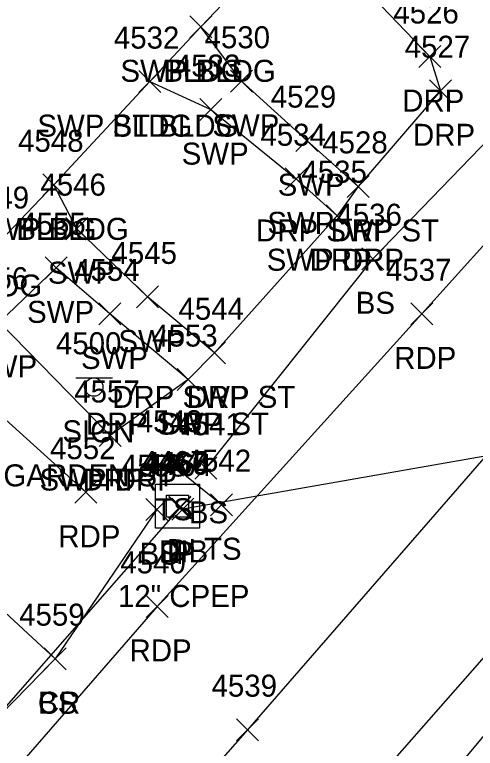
# Model space of a CAD drawing. Extents: x 1653135 to 1655489, y 602711 to 605684.
# Drawn here: x 1653195.4 to 1653237.3, y 604853.4 to 604920.1 of the extents above; entities that cross this region are included whole.
import ezdxf

# ---------------------------------------------------------------- set-up
doc = ezdxf.new("R2010")
doc.units = 0
for name, color, linetype in [('D_A', 7, 'Continuous'), ('D_C', 7, 'Continuous'), ('D_I', 7, 'Continuous'), ('D_TIC', 7, 'Continuous'), ('DCP', 7, 'Continuous'), ('DS', 7, 'Continuous'), ('L_A', 7, 'Continuous'), ('L_I', 7, 'Continuous'), ('L_TIC', 7, 'Continuous'), ('LBC', 7, 'Continuous'), ('LELB', 7, 'Continuous'), ('P_A', 7, 'Continuous'), ('P_I', 7, 'Continuous'), ('P_TIC', 7, 'Continuous'), ('PET', 7, 'Continuous'), ('PRC', 7, 'Continuous'), ('PSP', 7, 'Continuous'), ('R_A', 7, 'Continuous'), ('R_I', 7, 'Continuous'), ('R_TIC', 7, 'Continuous'), ('RDP', 7, 'Continuous'), ('RSW', 7, 'Continuous'), ('S_A', 7, 'Continuous'), ('S_C', 7, 'Continuous'), ('S_I', 7, 'Continuous'), ('SSGN', 7, 'Continuous')]:
    doc.layers.add(name, color=color, linetype=linetype)

msp = doc.modelspace()

# ---------------------------------------------------------------- linework, layer by layer
at = {"layer": 'D_TIC'}
for points in [[(1653209.407, 604874.267), (1653211.407, 604876.267)], [(1653211.407, 604874.267), (1653209.407, 604876.267)], [(1653209.407, 604874.267), (1653211.407, 604876.267)], [(1653211.407, 604874.267), (1653209.407, 604876.267)], [(1653209.428, 604874.33), (1653211.428, 604876.33)], [(1653211.428, 604874.33), (1653209.428, 604876.33)], [(1653209.428, 604874.33), (1653211.428, 604876.33)], [(1653211.428, 604874.33), (1653209.428, 604876.33)], [(1653209.682, 604874.162), (1653211.682, 604876.162)], [(1653211.682, 604874.162), (1653209.682, 604876.162)], [(1653209.682, 604874.162), (1653211.682, 604876.162)], [(1653211.682, 604874.162), (1653209.682, 604876.162)]]:
    msp.add_lwpolyline(points, dxfattribs=at)
at = {"layer": 'DCP'}
for points in [[(1653256.839, 604883.252), (1653210.682, 604875.162)], [(1653210.407, 604875.267), (1653189.689, 604851.651)]]:
    msp.add_lwpolyline(points, dxfattribs=at)
at = {"layer": 'DS'}
for p, q in [((1653208.191, 604877.425), (1653212.191, 604877.425)), ((1653208.191, 604873.425), (1653208.191, 604877.425)), ((1653212.191, 604877.425), (1653212.191, 604873.425)), ((1653209.191, 604874.425), (1653209.191, 604876.425)), ((1653209.191, 604876.425), (1653211.191, 604876.425)), ((1653211.191, 604876.425), (1653211.191, 604874.425)), ((1653210.196, 604875.426), (1653210.196, 604875.426)), ((1653210.196, 604875.426), (1653210.196, 604875.426)), ((1653211.191, 604874.425), (1653209.191, 604874.425)), ((1653212.191, 604873.425), (1653208.191, 604873.425))]:
    msp.add_line(p, q, dxfattribs=at)
at = {"layer": 'L_TIC'}
for points in [[(1653211.334, 604917.975), (1653213.334, 604919.975)], [(1653213.334, 604917.975), (1653211.334, 604919.975)], [(1653211.334, 604917.975), (1653213.334, 604919.975)], [(1653213.334, 604917.975), (1653211.334, 604919.975)], [(1653206.681, 604912.994), (1653208.681, 604914.994)], [(1653208.681, 604912.994), (1653206.681, 604914.994)], [(1653206.681, 604912.994), (1653208.681, 604914.994)], [(1653208.681, 604912.994), (1653206.681, 604914.994)], [(1653197.974, 604903.617), (1653199.974, 604905.617)], [(1653199.974, 604903.617), (1653197.974, 604905.617)], [(1653197.974, 604903.617), (1653199.974, 604905.617)], [(1653199.974, 604903.617), (1653197.974, 604905.617)], [(1653226.961, 604896.9), (1653228.961, 604898.9)], [(1653228.961, 604896.9), (1653226.961, 604898.9)], [(1653226.961, 604896.9), (1653228.961, 604898.9)], [(1653228.961, 604896.9), (1653226.961, 604898.9)], [(1653208.757, 604878.141), (1653210.757, 604880.141)], [(1653210.757, 604878.141), (1653208.757, 604880.141)], [(1653208.757, 604878.141), (1653210.757, 604880.141)], [(1653210.757, 604878.141), (1653208.757, 604880.141)], [(1653211.791, 604877.867), (1653213.791, 604879.867)], [(1653213.791, 604877.867), (1653211.791, 604879.867)], [(1653211.791, 604877.867), (1653213.791, 604879.867)], [(1653213.791, 604877.867), (1653211.791, 604879.867)], [(1653207.322, 604874.113), (1653209.322, 604876.113)], [(1653209.322, 604874.113), (1653207.322, 604876.113)], [(1653207.322, 604874.113), (1653209.322, 604876.113)], [(1653209.322, 604874.113), (1653207.322, 604876.113)], [(1653213.202, 604874.555), (1653215.202, 604876.555)], [(1653215.202, 604874.555), (1653213.202, 604876.555)], [(1653213.202, 604874.555), (1653215.202, 604876.555)], [(1653215.202, 604874.555), (1653213.202, 604876.555)], [(1653198.083, 604860.566), (1653200.083, 604862.566)], [(1653200.083, 604860.566), (1653198.083, 604862.566)], [(1653198.083, 604860.566), (1653200.083, 604862.566)], [(1653200.083, 604860.566), (1653198.083, 604862.566)]]:
    msp.add_lwpolyline(points, dxfattribs=at)
at = {"layer": 'LBC'}
msp.add_lwpolyline([(1653219.995, 604933.479), (1653223.222, 604930.634), (1653221.419, 604928.498), (1653212.334, 604918.975), (1653207.681, 604913.994), (1653198.974, 604904.617), (1653194.036, 604899.465), (1653189.6, 604903.61)], dxfattribs=at)
at = {"layer": 'LELB'}
for points in [[(1653332.421, 605013.129), (1653331.89, 605009.978), (1653320.371, 604996.763), (1653305.472, 604980.516), (1653289.085, 604960.14), (1653269.848, 604940.864), (1653246.658, 604917.207), (1653227.961, 604897.9), (1653212.791, 604878.867)], [(1653214.202, 604875.555), (1653209.757, 604879.141)], [(1653208.322, 604875.113), (1653199.083, 604861.566), (1653190.334, 604852.619), (1653187.506, 604849.984), (1653174.107, 604834.568), (1653155.579, 604815.865)]]:
    msp.add_lwpolyline(points, dxfattribs=at)
at = {"layer": 'P_TIC'}
for points in [[(1653231.406, 604891.896), (1653233.406, 604893.896)], [(1653233.406, 604891.896), (1653231.406, 604893.896)], [(1653231.406, 604891.896), (1653233.406, 604893.896)], [(1653233.406, 604891.896), (1653231.406, 604893.896)], [(1653200.882, 604875.692), (1653202.882, 604877.692)], [(1653202.882, 604875.692), (1653200.882, 604877.692)], [(1653200.882, 604875.692), (1653202.882, 604877.692)], [(1653202.882, 604875.692), (1653200.882, 604877.692)], [(1653207.357, 604865.317), (1653209.357, 604867.317)], [(1653209.357, 604865.317), (1653207.357, 604867.317)], [(1653207.357, 604865.317), (1653209.357, 604867.317)], [(1653209.357, 604865.317), (1653207.357, 604867.317)], [(1653198.083, 604860.566), (1653200.083, 604862.566)], [(1653200.083, 604860.566), (1653198.083, 604862.566)], [(1653198.083, 604860.566), (1653200.083, 604862.566)], [(1653200.083, 604860.566), (1653198.083, 604862.566)], [(1653215.566, 604854.116), (1653217.566, 604856.116)], [(1653217.566, 604854.116), (1653215.566, 604856.116)], [(1653215.566, 604854.116), (1653217.566, 604856.116)], [(1653217.566, 604854.116), (1653215.566, 604856.116)]]:
    msp.add_lwpolyline(points, dxfattribs=at)
at = {"layer": 'PET'}
for points in [[(1653570.485, 605162.786), (1653545.403, 605152.188), (1653524.597, 605144.335), (1653501.66, 605134.239), (1653492.53, 605129.6), (1653483.217, 605126.16), (1653461.507, 605114.196), (1653431.751, 605097.051), (1653402.439, 605074.196), (1653383.496, 605058.488), (1653369.863, 605045.734), (1653350.113, 605021.59), (1653336.009, 605007.549), (1653322.852, 604993.824), (1653302.166, 604970.774), (1653290.93, 604958.375), (1653272.167, 604938.098), (1653250.651, 604913.142), (1653232.406, 604892.896), (1653208.357, 604866.317), (1653177.81, 604831.245), (1653160.535, 604811.983)], [(1653576.316, 605135.262), (1653553.767, 605126.837), (1653519.051, 605112.425), (1653493.535, 605100.339), (1653468.833, 605088.005), (1653447.853, 605075.02), (1653427.596, 605061.865), (1653406.781, 605044.605), (1653388.905, 605027.698), (1653366.499, 605004.888), (1653354.584, 604992.023), (1653334.896, 604970.66), (1653318.046, 604952.193), (1653296.488, 604928.187), (1653274.624, 604903.556), (1653244.239, 604868.756), (1653225.75, 604847.701), (1653206.334, 604825.65), (1653179.645, 604794.747)], [(1653179.967, 604896.477), (1653201.882, 604876.692)]]:
    msp.add_lwpolyline(points, dxfattribs=at)
at = {"layer": 'PRC'}
for points in [[(1653576.361, 605149.524), (1653550.317, 605139.021), (1653518.724, 605125.668), (1653498.017, 605116.666), (1653468.035, 605101.489), (1653440.124, 605084.852), (1653411.973, 605063.454), (1653392.179, 605045.924), (1653380.925, 605035.31), (1653360.25, 605013.969), (1653332.49, 604984.793), (1653311.146, 604961.542), (1653300.12, 604949.228), (1653281.614, 604928.677), (1653260.957, 604905.277), (1653242.089, 604884.435), (1653216.566, 604855.116), (1653187.493, 604822.135), (1653170.081, 604802.31)], [(1653199.083, 604861.566), (1653169.543, 604888.888)]]:
    msp.add_lwpolyline(points, dxfattribs=at)
at = {"layer": 'PSP'}
msp.add_lwpolyline([(1653577.495, 605132.222), (1653555.735, 605120.61), (1653541.776, 605115.966), (1653532.613, 605114.781), (1653532.247, 605110.88), (1653522.733, 605106.898), (1653507.697, 605103.522), (1653493.111, 605096.605), (1653471.403, 605083.027), (1653450.958, 605070.25), (1653430.837, 605057.523), (1653410.321, 605040.006), (1653392.797, 605023.713), (1653372.132, 605001.835), (1653359.179, 604987.803), (1653339.003, 604967.206), (1653322.133, 604948.589), (1653300.744, 604925.192), (1653278.521, 604900.611), (1653247.528, 604865.908), (1653229.566, 604844.432), (1653209.3, 604822.581), (1653182.433, 604791.771)], dxfattribs=at)
at = {"layer": 'R_TIC'}
for points in [[(1653211.334, 604917.975), (1653213.334, 604919.975)], [(1653213.334, 604917.975), (1653211.334, 604919.975)], [(1653211.334, 604917.975), (1653213.334, 604919.975)], [(1653213.334, 604917.975), (1653211.334, 604919.975)], [(1653232.134, 604915.272), (1653234.134, 604917.272)], [(1653234.134, 604915.272), (1653232.134, 604917.272)], [(1653232.134, 604915.272), (1653234.134, 604917.272)], [(1653234.134, 604915.272), (1653232.134, 604917.272)], [(1653206.681, 604912.994), (1653208.681, 604914.994)], [(1653208.681, 604912.994), (1653206.681, 604914.994)], [(1653206.681, 604912.994), (1653208.681, 604914.994)], [(1653208.681, 604912.994), (1653206.681, 604914.994)], [(1653215.009, 604913.024), (1653217.009, 604915.024)], [(1653217.009, 604913.024), (1653215.009, 604915.024)], [(1653215.009, 604913.024), (1653217.009, 604915.024)], [(1653217.009, 604913.024), (1653215.009, 604915.024)], [(1653233.115, 604912.162), (1653235.115, 604914.162)], [(1653235.115, 604912.162), (1653233.115, 604914.162)], [(1653233.115, 604912.162), (1653235.115, 604914.162)], [(1653235.115, 604912.162), (1653233.115, 604914.162)], [(1653212.222, 604910.455), (1653214.222, 604912.455)], [(1653214.222, 604910.455), (1653212.222, 604912.455)], [(1653212.222, 604910.455), (1653214.222, 604912.455)], [(1653214.222, 604910.455), (1653212.222, 604912.455)], [(1653220.944, 604907.632), (1653222.944, 604909.632)], [(1653222.944, 604907.632), (1653220.944, 604909.632)], [(1653220.944, 604907.632), (1653222.944, 604909.632)], [(1653222.944, 604907.632), (1653220.944, 604909.632)], [(1653220.002, 604904.164), (1653222.002, 604906.164)], [(1653222.002, 604904.164), (1653220.002, 604906.164)], [(1653220.002, 604904.164), (1653222.002, 604906.164)], [(1653222.002, 604904.164), (1653220.002, 604906.164)], [(1653197.974, 604903.617), (1653199.974, 604905.617)], [(1653199.974, 604903.617), (1653197.974, 604905.617)], [(1653197.974, 604903.617), (1653199.974, 604905.617)], [(1653199.974, 604903.617), (1653197.974, 604905.617)], [(1653225.618, 604903.474), (1653227.618, 604905.474)], [(1653227.618, 604903.474), (1653225.618, 604905.474)], [(1653225.618, 604903.474), (1653227.618, 604905.474)], [(1653227.618, 604903.474), (1653225.618, 604905.474)], [(1653225.618, 604903.474), (1653227.618, 604905.474)], [(1653227.618, 604903.474), (1653225.618, 604905.474)], [(1653225.618, 604903.474), (1653227.618, 604905.474)], [(1653227.618, 604903.474), (1653225.618, 604905.474)], [(1653223.727, 604900.812), (1653225.727, 604902.812)], [(1653225.727, 604900.812), (1653223.727, 604902.812)], [(1653223.727, 604900.812), (1653225.727, 604902.812)], [(1653225.727, 604900.812), (1653223.727, 604902.812)], [(1653223.727, 604900.812), (1653225.727, 604902.812)], [(1653225.727, 604900.812), (1653223.727, 604902.812)], [(1653223.727, 604900.812), (1653225.727, 604902.812)], [(1653225.727, 604900.812), (1653223.727, 604902.812)], [(1653200.061, 604899.635), (1653202.061, 604901.635)], [(1653202.061, 604899.635), (1653200.061, 604901.635)], [(1653200.061, 604899.635), (1653202.061, 604901.635)], [(1653202.061, 604899.635), (1653200.061, 604901.635)], [(1653198.171, 604896.077), (1653200.171, 604898.077)], [(1653200.171, 604896.077), (1653198.171, 604898.077)], [(1653198.171, 604896.077), (1653200.171, 604898.077)], [(1653200.171, 604896.077), (1653198.171, 604898.077)], [(1653206.465, 604893.435), (1653208.465, 604895.435)], [(1653208.465, 604893.435), (1653206.465, 604895.435)], [(1653206.465, 604893.435), (1653208.465, 604895.435)], [(1653208.465, 604893.435), (1653206.465, 604895.435)], [(1653203.069, 604891.891), (1653205.069, 604893.891)], [(1653205.069, 604891.891), (1653203.069, 604893.891)], [(1653203.069, 604891.891), (1653205.069, 604893.891)], [(1653205.069, 604891.891), (1653203.069, 604893.891)], [(1653212.552, 604888.356), (1653214.552, 604890.356)], [(1653214.552, 604888.356), (1653212.552, 604890.356)], [(1653212.552, 604888.356), (1653214.552, 604890.356)], [(1653214.552, 604888.356), (1653212.552, 604890.356)], [(1653212.552, 604888.356), (1653214.552, 604890.356)], [(1653214.552, 604888.356), (1653212.552, 604890.356)], [(1653212.552, 604888.356), (1653214.552, 604890.356)], [(1653214.552, 604888.356), (1653212.552, 604890.356)], [(1653210.159, 604885.923), (1653212.159, 604887.923)], [(1653212.159, 604885.923), (1653210.159, 604887.923)], [(1653210.159, 604885.923), (1653212.159, 604887.923)], [(1653212.159, 604885.923), (1653210.159, 604887.923)], [(1653210.159, 604885.923), (1653212.159, 604887.923)], [(1653212.159, 604885.923), (1653210.159, 604887.923)], [(1653210.159, 604885.923), (1653212.159, 604887.923)], [(1653212.159, 604885.923), (1653210.159, 604887.923)], [(1653203.08, 604880.842), (1653205.08, 604882.842)], [(1653205.08, 604880.842), (1653203.08, 604882.842)], [(1653203.08, 604880.842), (1653205.08, 604882.842)], [(1653205.08, 604880.842), (1653203.08, 604882.842)], [(1653203.08, 604880.842), (1653205.08, 604882.842)], [(1653205.08, 604880.842), (1653203.08, 604882.842)], [(1653203.08, 604880.842), (1653205.08, 604882.842)], [(1653205.08, 604880.842), (1653203.08, 604882.842)]]:
    msp.add_lwpolyline(points, dxfattribs=at)
at = {"layer": 'RDP'}
msp.add_lwpolyline([(1653221.419, 604928.498), (1653233.134, 604916.272), (1653234.115, 604913.162), (1653226.618, 604904.474), (1653224.727, 604901.812), (1653213.552, 604889.356), (1653211.159, 604886.923), (1653204.08, 604881.842)], dxfattribs=at)
at = {"layer": 'RSW'}
for points in [[(1653226.618, 604904.474), (1653221.944, 604908.632), (1653216.009, 604914.024), (1653212.334, 604918.975)], [(1653207.681, 604913.994), (1653213.222, 604911.455), (1653221.002, 604905.164), (1653224.727, 604901.812)], [(1653213.552, 604889.356), (1653207.465, 604894.435), (1653201.061, 604900.635), (1653198.974, 604904.617)], [(1653211.159, 604886.923), (1653204.069, 604892.891), (1653199.171, 604897.077), (1653193.995, 604892.133), (1653204.08, 604881.842)]]:
    msp.add_lwpolyline(points, dxfattribs=at)
at = {"layer": 'SSGN'}
for p, q in [((1653200.954, 604887.077), (1653204.287, 604887.077)), ((1653202.6, 604886.244), (1653202.6, 604886.244))]:
    msp.add_line(p, q, dxfattribs=at)
msp.add_circle((1653202.6, 604886.244), 0.833, dxfattribs=at)

# ---------------------------------------------------------------- texts
at = {"layer": 'D_A'}
for s, p in [('DIB', (1653208.53, 604870.33)), ('DIB', (1653208.53, 604870.33)), ('DI', (1653209.252, 604870.426)), ('P', (1653209.785, 604870.267)), ('P', (1653209.785, 604870.267)), ('P', (1653210.06, 604870.162)), ('P', (1653210.06, 604870.162))]:
    msp.add_text(s, height=2, dxfattribs=at).set_placement(p)
at = {"layer": 'D_C'}
msp.add_text('12" CPEP', height=2, dxfattribs=at).set_placement((1653204.793, 604866.267))
msp.add_text('12" CPEP', height=2, dxfattribs=at).set_placement((1653204.793, 604866.267))
at = {"layer": 'D_I'}
for s, p in [('4467', (1653206.889, 604878.426)), ('4466', (1653207.045, 604878.267)), ('4466', (1653207.045, 604878.267)), ('4465', (1653207.121, 604878.33)), ('4465', (1653207.121, 604878.33)), ('4464', (1653207.375, 604878.162)), ('4464', (1653207.375, 604878.162))]:
    msp.add_text(s, height=2, dxfattribs=at).set_placement(p)
at = {"layer": 'L_A'}
for s, p in [('BLDG', (1653208.924, 604913.975)), ('BLDG', (1653208.924, 604913.975)), ('BLDG', (1653204.271, 604908.994)), ('BLDG', (1653204.271, 604908.994)), ('BLDG', (1653195.565, 604899.617)), ('BLDG', (1653195.565, 604899.617)), ('BLDG', (1653190.627, 604894.465)), ('BLDG', (1653190.627, 604894.465)), ('BS', (1653226.402, 604892.9)), ('BS', (1653226.402, 604892.9)), ('TS', (1653208.167, 604874.141)), ('TS', (1653208.167, 604874.141)), ('BS', (1653211.232, 604873.867)), ('BS', (1653211.232, 604873.867)), ('TS', (1653212.612, 604870.555)), ('TS', (1653212.612, 604870.555)), ('BS', (1653206.763, 604870.113)), ('BS', (1653206.763, 604870.113)), ('BS', (1653197.524, 604856.566)), ('BS', (1653197.524, 604856.566))]:
    msp.add_text(s, height=2, dxfattribs=at).set_placement(p)
at = {"layer": 'L_I'}
for s, p in [('4532', (1653204.421, 604916.994)), ('4532', (1653204.421, 604916.994)), ('4548', (1653195.715, 604907.617)), ('4548', (1653195.715, 604907.617)), ('4549', (1653190.769, 604902.465)), ('4549', (1653190.769, 604902.465)), ('4536', (1653224.646, 604900.9)), ('4536', (1653224.646, 604900.9)), ('4543', (1653206.498, 604882.141)), ('4543', (1653206.498, 604882.141)), ('4541', (1653210.098, 604881.867)), ('4541', (1653210.098, 604881.867)), ('4542', (1653210.943, 604878.555)), ('4542', (1653210.943, 604878.555)), ('4558', (1653205.063, 604878.113)), ('4558', (1653205.063, 604878.113)), ('4559', (1653195.815, 604864.566)), ('4559', (1653195.815, 604864.566))]:
    msp.add_text(s, height=2, dxfattribs=at).set_placement(p)
at = {"layer": 'P_A'}
for s, p in [('RDP', (1653229.894, 604887.896)), ('RDP', (1653229.894, 604887.896)), ('RDP', (1653199.37, 604871.692)), ('RDP', (1653199.37, 604871.692)), ('RDP', (1653205.845, 604861.317)), ('RDP', (1653205.845, 604861.317)), ('CR', (1653197.516, 604856.566)), ('CR', (1653197.516, 604856.566))]:
    msp.add_text(s, height=2, dxfattribs=at).set_placement(p)
at = {"layer": 'P_I'}
for s, p in [('4537', (1653229.146, 604895.896)), ('4537', (1653229.146, 604895.896)), ('4552', (1653198.622, 604879.692)), ('4552', (1653198.622, 604879.692)), ('4540', (1653205.011, 604869.317)), ('4540', (1653205.011, 604869.317)), ('4559', (1653195.815, 604864.566)), ('4559', (1653195.815, 604864.566)), ('4539', (1653213.298, 604858.116)), ('4539', (1653213.298, 604858.116))]:
    msp.add_text(s, height=2, dxfattribs=at).set_placement(p)
at = {"layer": 'R_A'}
for s, p in [('SWP BLDG', (1653205.019, 604913.975)), ('SWP BLDG', (1653205.019, 604913.975)), ('DRP', (1653230.622, 604911.272)), ('DRP', (1653230.622, 604911.272)), ('SWP ST BLDG', (1653197.468, 604908.994)), ('SWP ST BLDG', (1653197.468, 604908.994)), ('SWP', (1653213.371, 604909.024)), ('SWP', (1653213.371, 604909.024)), ('DRP', (1653231.604, 604908.162)), ('DRP', (1653231.604, 604908.162)), ('SWP', (1653210.585, 604906.455)), ('SWP', (1653210.585, 604906.455)), ('SWP', (1653219.306, 604903.632)), ('SWP', (1653219.306, 604903.632)), ('SWP', (1653218.364, 604900.164)), ('SWP', (1653218.364, 604900.164)), ('SWP BLDG', (1653191.659, 604899.617)), ('SWP BLDG', (1653191.659, 604899.617)), ('DRP SWP ST', (1653217.335, 604899.474)), ('DRP SWP ST', (1653217.335, 604899.474)), ('DRP', (1653224.106, 604899.474)), ('DRP', (1653224.106, 604899.474)), ('SWP DRP', (1653218.309, 604896.812)), ('SWP DRP', (1653218.309, 604896.812)), ('DRP', (1653222.215, 604896.812)), ('DRP', (1653222.215, 604896.812)), ('SWP', (1653198.423, 604895.635)), ('SWP', (1653198.423, 604895.635)), ('SWP', (1653196.533, 604892.077)), ('SWP', (1653196.533, 604892.077)), ('SWP', (1653204.827, 604889.435)), ('SWP', (1653204.827, 604889.435)), ('SWP', (1653201.431, 604887.891)), ('SWP', (1653201.431, 604887.891)), ('SWP', (1653191.357, 604887.133)), ('SWP', (1653191.357, 604887.133)), ('DRP SWP ST', (1653204.269, 604884.356)), ('DRP SWP ST', (1653204.269, 604884.356)), ('DRP', (1653211.041, 604884.356)), ('DRP', (1653211.041, 604884.356)), ('DRP SWP ST', (1653201.876, 604881.923)), ('DRP SWP ST', (1653201.876, 604881.923)), ('DRP', (1653208.648, 604881.923)), ('DRP', (1653208.648, 604881.923)), ('SWP DRP', (1653197.663, 604876.842)), ('SWP DRP', (1653197.663, 604876.842)), ('DRP', (1653201.568, 604876.842)), ('DRP', (1653201.568, 604876.842))]:
    msp.add_text(s, height=2, dxfattribs=at).set_placement(p)
at = {"layer": 'R_I'}
for s, p in [('4526', (1653229.819, 604919.272)), ('4526', (1653229.819, 604919.272)), ('4532', (1653204.421, 604916.994)), ('4532', (1653204.421, 604916.994)), ('4530', (1653212.663, 604917.024)), ('4530', (1653212.663, 604917.024)), ('4527', (1653230.856, 604916.162)), ('4527', (1653230.856, 604916.162)), ('4533', (1653209.963, 604914.455)), ('4533', (1653209.963, 604914.455)), ('4529', (1653218.676, 604911.632)), ('4529', (1653218.676, 604911.632)), ('4534', (1653217.742, 604908.164)), ('4534', (1653217.742, 604908.164)), ('4548', (1653195.715, 604907.617)), ('4548', (1653195.715, 604907.617)), ('4528', (1653223.358, 604907.474)), ('4528', (1653223.358, 604907.474)), ('4528', (1653223.358, 604907.474)), ('4528', (1653223.358, 604907.474)), ('4535', (1653221.467, 604904.812)), ('4535', (1653221.467, 604904.812)), ('4535', (1653221.467, 604904.812)), ('4535', (1653221.467, 604904.812)), ('4546', (1653197.746, 604903.635)), ('4546', (1653197.746, 604903.635)), ('4555', (1653195.912, 604900.077)), ('4555', (1653195.912, 604900.077)), ('4545', (1653204.205, 604897.435)), ('4545', (1653204.205, 604897.435)), ('4554', (1653200.809, 604895.891)), ('4554', (1653200.809, 604895.891)), ('4556', (1653190.68, 604895.133)), ('4556', (1653190.68, 604895.133)), ('4544', (1653210.293, 604892.356)), ('4544', (1653210.293, 604892.356)), ('4544', (1653210.293, 604892.356)), ('4544', (1653210.293, 604892.356)), ('4553', (1653207.9, 604889.923)), ('4553', (1653207.9, 604889.923)), ('4553', (1653207.9, 604889.923)), ('4553', (1653207.9, 604889.923)), ('4557', (1653200.821, 604884.842)), ('4557', (1653200.821, 604884.842)), ('4557', (1653200.821, 604884.842)), ('4557', (1653200.821, 604884.842))]:
    msp.add_text(s, height=2, dxfattribs=at).set_placement(p)
at = {"layer": 'S_A'}
msp.add_text('SIGN', height=2, dxfattribs=at).set_placement((1653199.738, 604881.223))
at = {"layer": 'S_C'}
msp.add_text('GARDEN ST', height=2, dxfattribs=at).set_placement((1653194.384, 604877.223))
at = {"layer": 'S_I'}
msp.add_text('4500', height=2, dxfattribs=at).set_placement((1653199.156, 604889.223))

doc.saveas('drawing.dxf')
